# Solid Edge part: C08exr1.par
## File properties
Author: CADCIM
Template: normal.par
Last saved by: CADCIM
Revision: 10
Application: Solid Edge
Accuracy: 0.99
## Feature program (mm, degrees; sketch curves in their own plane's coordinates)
pattern "unnamed Pattern 1"
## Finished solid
Body 1: solid body, 34 faces, 81 edges, 46 vertices.
  Faces by surface: plane 28, cylinder 6
  Edges by curve: line 67, circle 14
Bounding box of the edges (mm): 170.000 x 92.000 x 106.000, from (30, -46, -30) to (200, 46, 76).
Cylindrical faces by radius (mm): R8 x2, R16 x2, R18 x1, R30 x1
Planar faces by outward normal: +x 3, +y 5, +z 4, -x 5, -y 5, -z 4, oblique 2
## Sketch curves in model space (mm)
circle centre (60, 0, 0) radius 18
line (182, 0, -4) -> (164, 0, -4)
line (104, 0, -30) -> (60, 0, -30)
arc centre (60, 0, 0) radius 30 from (60, 0, 30) through (30.0132, 0, -0.889) to (60, 0, -30)
arc centre (60, 0, 0) radius 30 from (60, 0, 30) through (89.9868, 0, -0.889) to (60, 0, -30)
line (142, 0, 36) -> (182, 0, 76)
line (142, 0, 36) -> (182, 0, 36)
line (104, 0, -30) -> (164, 0, -4)
line (182, 0, 76) -> (182, 0, 36)
line (182, 0, -4) -> (182, 0, 36)
line (142, 0, 30) -> (142, 0, 36)
line (60, 0, 30) -> (142, 0, 30)
line (104, 0, 18) -> (104, 0, -30)
line (164, 0, 18) -> (104, 0, 18)
line (164, 0, -4) -> (164, 0, 18)
line (200, 0, -4) -> (182, 0, -4)
line (200, 0, 76) -> (200, 0, -4)
line (182, 0, 76) -> (200, 0, 76)
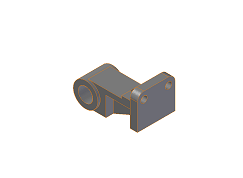
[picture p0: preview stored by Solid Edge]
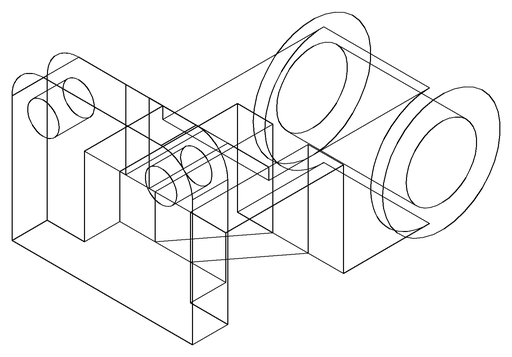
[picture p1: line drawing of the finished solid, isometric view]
